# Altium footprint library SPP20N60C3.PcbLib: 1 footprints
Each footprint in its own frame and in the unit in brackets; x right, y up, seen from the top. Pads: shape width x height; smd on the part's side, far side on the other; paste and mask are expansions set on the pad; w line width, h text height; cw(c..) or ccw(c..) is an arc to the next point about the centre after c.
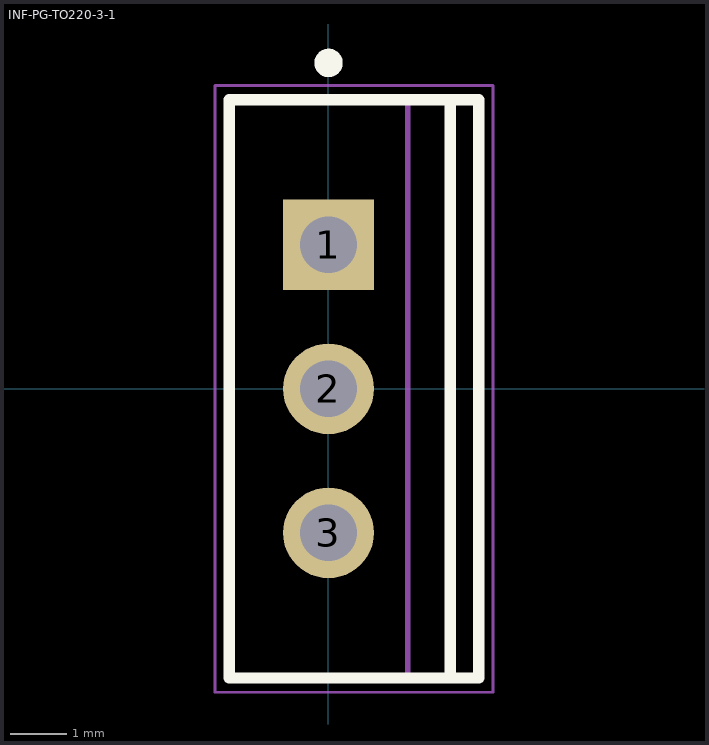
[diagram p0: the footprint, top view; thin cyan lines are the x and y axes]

## INF-PG-TO220-3-1 [mm] "FM, 3-Leads, Body 10x4.4mm, Pitch 2.54mm"
height 20.7
pads (3):
  rect 1.6x1.6 hole 1: 1(0,2.54)
  round 1.6 hole 1: 2(0,0) 3(0,-2.54)
Top Overlay:
  circle w0.25: c0,5.75 r0.125
  lines w0.2: 2.15,-5.1 2.15,5.1 ; -1.75,-5.1 2.65,-5.1 2.65,5.1 -1.75,5.1 -1.75,-5.1
Mechanical 13:
  lines w0.1: 1.4,-5.1 1.4,5.1 ; -1.75,-5.1 -1.75,5.1 2.65,5.1 2.65,-5.1 -1.75,-5.1
Mechanical 15:
  lines w0.05: -2,-5.35 -2,5.35 2.9,5.35 2.9,-5.35 -2,-5.35
  lines w0.1: -0.5,0 0.5,0 ; 0,-0.5 0,0.5
3D body: height 4.35, standoff 0, extent -0.25,2.015 0.25,3.065
3D body: height 0, standoff -1.6, extent -0.25,2.165 0.25,2.915
3D body: height 4.35, standoff 0, extent -0.25,-0.525 0.25,0.525
3D body: height 0, standoff -1.6, extent -0.25,-0.375 0.25,0.375
3D body: height 4.35, standoff 0, extent -0.25,-3.065 0.25,-2.015
3D body: height 0, standoff -1.6, extent -0.25,-2.915 0.25,-2.165
3D body: height 14.3, standoff 4.35, extent -1.75,-5.1 2.65,5.1
3D body: height 16.08, standoff 14.3, extent 1.4,-4.95 2.65,4.95
3D body: height 16.12, standoff 16.08, extent 1.4,0.356 2.65,4.95
3D body: height 16.12, standoff 16.08, extent 1.4,-4.95 2.65,-0.356
3D body: height 19.73, standoff 19.69, extent 1.4,0.356 2.65,4.95
3D body: height 19.73, standoff 19.69, extent 1.4,-4.95 2.65,-0.356
3D body: height 16.22, standoff 16.11, extent 1.4,0.698 2.65,4.95
3D body: height 16.22, standoff 16.11, extent 1.4,-4.95 2.65,-0.698
3D body: height 19.69, standoff 19.59, extent 1.4,0.698 2.65,4.95
3D body: height 19.69, standoff 19.59, extent 1.4,-4.95 2.65,-0.698
3D body: height 16.39, standoff 16.21, extent 1.4,1.014 2.65,4.95
3D body: height 16.39, standoff 16.21, extent 1.4,-4.95 2.65,-1.014
3D body: height 19.59, standoff 19.42, extent 1.4,1.014 2.65,4.95
3D body: height 19.59, standoff 19.42, extent 1.4,-4.95 2.65,-1.014
3D body: height 16.61, standoff 16.38, extent 1.4,1.29 2.65,4.95
3D body: height 16.61, standoff 16.38, extent 1.4,-4.95 2.65,-1.29
3D body: height 19.42, standoff 19.19, extent 1.4,1.29 2.65,4.95
3D body: height 19.42, standoff 19.19, extent 1.4,-4.95 2.65,-1.29
3D body: height 16.89, standoff 16.61, extent 1.4,1.517 2.65,4.95
3D body: height 16.89, standoff 16.61, extent 1.4,-4.95 2.65,-1.517
3D body: height 19.2, standoff 18.91, extent 1.4,1.517 2.65,4.95
3D body: height 19.2, standoff 18.91, extent 1.4,-4.95 2.65,-1.517
3D body: height 17.21, standoff 16.89, extent 1.4,1.686 2.65,4.95
3D body: height 17.21, standoff 16.89, extent 1.4,-4.95 2.65,-1.686
3D body: height 18.92, standoff 18.6, extent 1.4,1.686 2.65,4.95
3D body: height 18.92, standoff 18.6, extent 1.4,-4.95 2.65,-1.686
3D body: height 17.55, standoff 17.2, extent 1.4,1.79 2.65,4.95
3D body: height 17.55, standoff 17.2, extent 1.4,-4.95 2.65,-1.79
3D body: height 18.6, standoff 18.26, extent 1.4,1.79 2.65,4.95
3D body: height 18.6, standoff 18.26, extent 1.4,-4.95 2.65,-1.79
3D body: height 17.9, standoff 17.54, extent 1.4,1.825 2.65,4.95
3D body: height 17.9, standoff 17.54, extent 1.4,-4.95 2.65,-1.825
3D body: height 18.26, standoff 17.9, extent 1.4,1.825 2.65,4.95
3D body: height 18.26, standoff 17.9, extent 1.4,-4.95 2.65,-1.825
3D body: height 20.7, standoff 19.73, extent 1.4,-4.95 2.65,4.95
